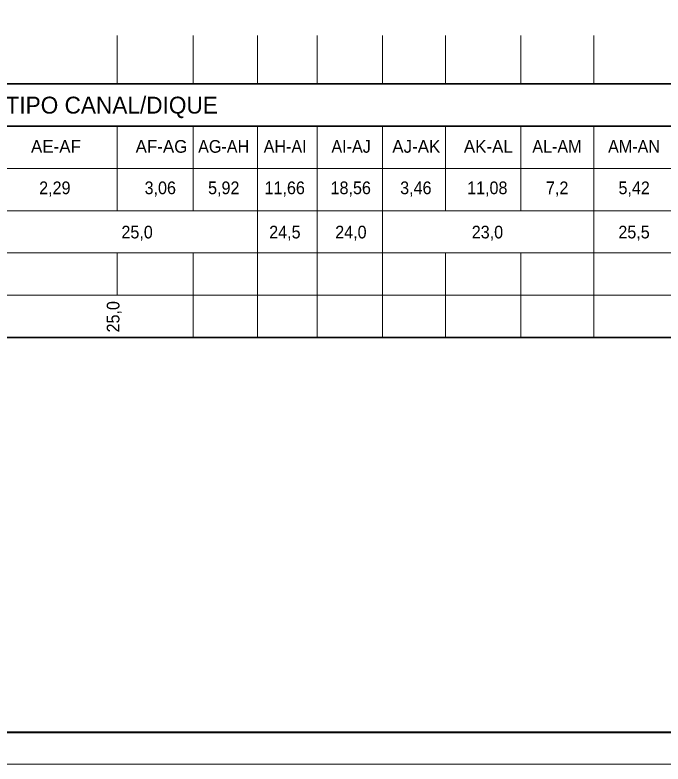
# Model space of a CAD drawing. Extents: x 8458 to 9360, y 19921 to 20366.
# Drawn here: x 9028.9 to 9182.2, y 19920.7 to 20097.9 of the extents above; entities that cross this region are included whole.
import ezdxf

# ---------------------------------------------------------------- set-up
doc = ezdxf.new("R2010")
doc.units = 0
doc.header["$LTSCALE"] = 1.2
doc.layers.add('1', color=7, linetype='Continuous', lineweight=40)
doc.layers.add('5', color=7, linetype='Continuous', lineweight=13)

msp = doc.modelspace()

# ---------------------------------------------------------------- linework, layer by layer
at = {"layer": '1'}
msp.add_line((8495.27, 19928.17), (9352.57, 19928.17), dxfattribs=at)
at = {"layer": '1', "lineweight": 13}
msp.add_lwpolyline([(8457.77, 19920.67), (9360.07, 19920.67), (9360.07, 20366.17), (8457.77, 20366.17)], close=True, dxfattribs=at)
at = {"layer": '5'}
for p, q in [((9053.06, 20093.05), (9053.06, 20081.61)), ((9071.02, 20093.05), (9071.02, 20081.61)), ((9086.2, 20093.05), (9086.2, 20081.61)), ((9100.34, 20093.05), (9100.34, 20081.61)), ((9115.78, 20093.05), (9115.78, 20081.61)), ((9130.7, 20093.05), (9130.7, 20081.61)), ((9148.5, 20093.05), (9148.5, 20081.61)), ((9165.78, 20093.05), (9165.78, 20081.61)), ((9053.06, 20071.61), (9053.06, 20051.61)), ((9071.02, 20071.61), (9071.02, 20051.61)), ((9086.2, 20071.61), (9086.2, 20021.61)), ((9100.34, 20071.61), (9100.34, 20021.61)), ((9115.78, 20071.61), (9115.78, 20021.61)), ((9130.7, 20071.61), (9130.7, 20051.61)), ((9148.5, 20071.61), (9148.5, 20051.61)), ((9165.78, 20071.61), (9165.78, 20021.61)), ((8517.12, 20061.6), (9319.97, 20061.61)), ((8517.12, 20051.6), (9319.97, 20051.61)), ((8517.12, 20041.6), (9319.97, 20041.61)), ((8535.69, 20041.6), (9319.97, 20041.61)), ((9053.06, 20041.61), (9053.06, 20031.61)), ((9071.02, 20041.61), (9071.02, 20021.61)), ((9130.7, 20041.61), (9130.7, 20021.61)), ((9148.5, 20041.61), (9148.5, 20021.61)), ((8517.12, 20031.6), (9319.97, 20031.61))]:
    msp.add_line(p, q, dxfattribs=at)
at = {"layer": '5', "lineweight": 35}
for p, q in [((8585.69, 20081.6), (9319.97, 20081.61)), ((8585.69, 20071.6), (9319.97, 20071.61)), ((8517.12, 20021.6), (9319.97, 20021.61))]:
    msp.add_line(p, q, dxfattribs=at)

# ---------------------------------------------------------------- texts
at = {"layer": '5'}
for s, height, p in [('CANAL DE INTERLIGAÇÃO TIPO CANAL/DIQUE', 4, (8957.07, 20074.59)), ('AE-AF', 3, (9032.64, 20065.32)), ('AF-AG', 3, (9057.39, 20065.32)), ('AJ-AK', 3, (9118.12, 20065.32)), ('AK-AL', 3, (9135.04, 20065.32))]:
    msp.add_text(s, height=height, dxfattribs=at).set_placement(p)
at = {"layer": '5', "width": 0.95}
for s, p in [('AG-AH', (9072.19, 20065.32)), ('AH-AI', (9087.69, 20065.32)), ('AI-AJ', (9103.72, 20065.32)), ('AL-AM', (9151.25, 20065.32)), ('AM-AN', (9169.17, 20065.32)), ('2,29', (9034.58, 20055.52)), ('3,06', (9059.52, 20055.52)), ('5,92', (9074.54, 20055.52)), ('11,66', (9087.9, 20055.52)), ('18,56', (9103.52, 20055.52)), ('3,46', (9119.98, 20055.52)), ('11,08', (9135.82, 20055.52)), ('7,2', (9154.47, 20055.52)), ('5,42', (9171.63, 20055.52)), ('25,0', (9054.04, 20045.05)), ('24,5', (9089, 20045.05)), ('24,0', (9104.62, 20045.05)), ('23,0', (9136.92, 20045.05)), ('25,5', (9171.6, 20045.05))]:
    msp.add_text(s, height=3, dxfattribs=at).set_placement(p)
msp.add_text('25,0', height=3, rotation=90, dxfattribs=at).set_placement((9053.57, 20022.8))

doc.saveas('drawing.dxf')
